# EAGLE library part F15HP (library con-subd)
SUB-D
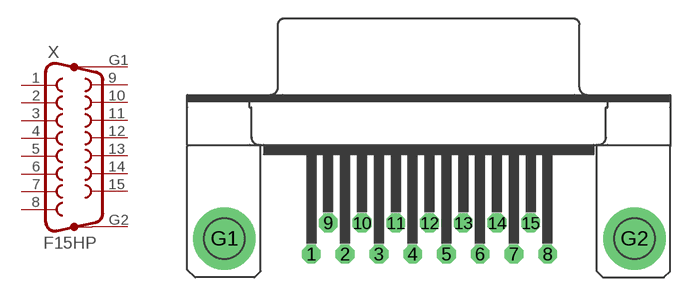
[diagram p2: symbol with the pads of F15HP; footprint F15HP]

Designator prefix X

## F15HP (OC_FARNELL: unknown; OC_NEWARK: unknown)  [F15HP]
1  1  pas
2  2  pas
3  3  pas
4  4  pas
5  5  pas
6  6  pas
7  7  pas
8  8  pas
9  9  pas
10  10  pas
11  11  pas
12  12  pas
13  13  pas
14  14  pas
15  15  pas
G1  G1  pas
G2  G2  pas

## Footprint F15HP (pad centres in mm)
SUB-D
drill 1.016 octagon: 1 -9.601,-1.27; 2 -6.858,-1.27; 3 -4.115,-1.27; 4 -1.372,-1.27; 5 1.372,-1.27; 6 4.115,-1.27; 7 6.858,-1.27; 8 9.601,-1.27; 9 -8.23,1.27; 10 -5.486,1.27; 11 -2.743,1.27; 12 0,1.27; 13 2.743,1.27; 14 5.486,1.27; 15 8.23,1.27
drill 3.302 pad 5.08 round: G1 -16.662,0; G2 16.662,0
